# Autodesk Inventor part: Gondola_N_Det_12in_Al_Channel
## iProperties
Shininess: 64.0
Length Units: 11272
Angle Units: 11279
Time Units: 11290
Mass Units: 11286
Length Display Precision: 3
Angle Display Precision: 2
Compacted: True
Part Number: Gondola_N_Det_12in_Al_Channel
Document SubType Name: Modeling
Created: 2004-12
Designer: John Blackburn
Material: Aluminum-6061
Description: AL. Assoc. 8" 6061-T6 Channel
Manufacturer: Standard
Standards Organization: Custom
Density: 0.0
Volumn: 0.0
Area: 0.0
PropertySet Name: Model Information
Control State: 0
Master: False
Checked Out: False
Author: John Blackburn
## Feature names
1. Extrusion1
2. Hole1
3. Hole2
4. Hole3
5. Hole4
6. Hole5
7. Hole6
8. Hole8
9. Extrusion2
10. Hole9
11. Hole10
12. Hole11
13. Extrusion3
